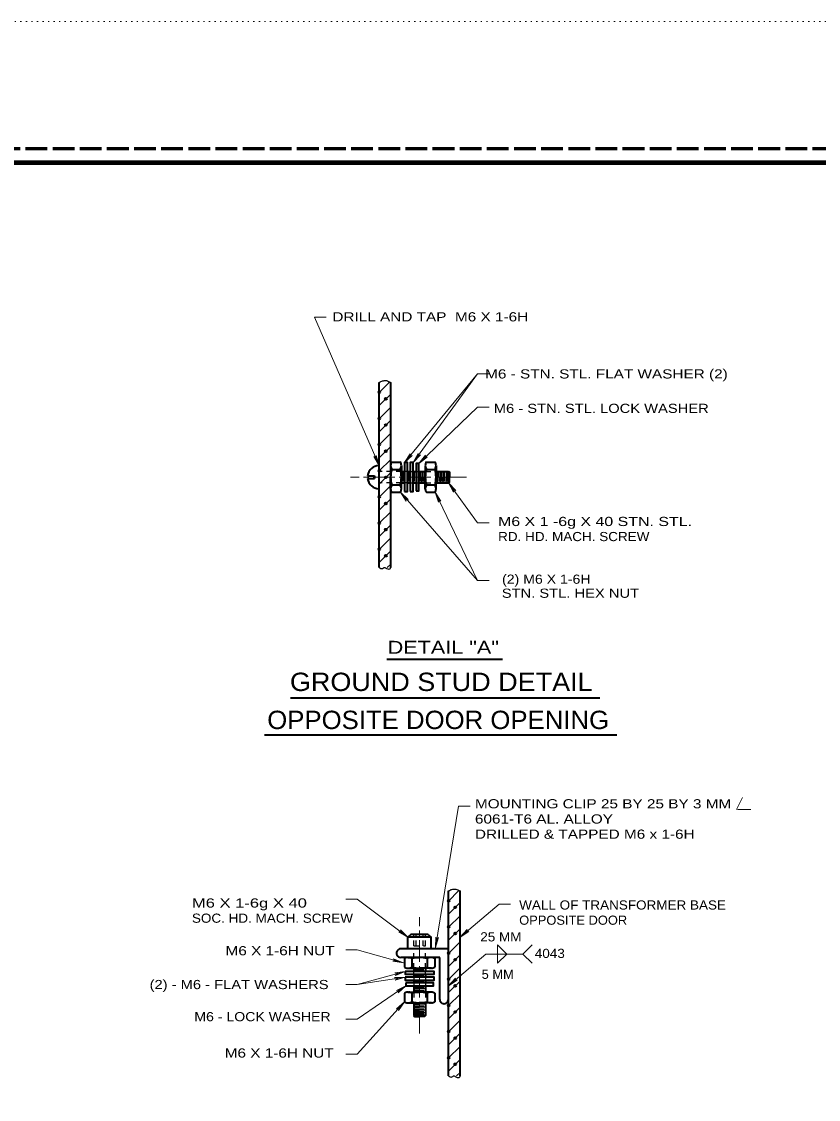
# Model space of a CAD drawing. Extents: x 312583 to 312854, y 144419 to 144597.
# Drawn here: x 312721.4 to 312787.4, y 144507.4 to 144596.8 of the extents above; entities that cross this region are included whole.
import ezdxf
from ezdxf.enums import TextEntityAlignment as Align

# ---------------------------------------------------------------- set-up
doc = ezdxf.new("R2010")
doc.units = 0
doc.header["$LTSCALE"] = 0.3
doc.header["$PDMODE"] = 32
doc.header["$PDSIZE"] = 0.15
for name, pattern in [('DOTTED', [1.5, 0.3, -1.2]), ('LONG_DASH_SHORT_DASH', [9.9, 6, -1.2, 1.5, -1.2]), ('LONG_DASHED', [7.5, 6, -1.5]), ('SHORT_DASHED', [2.7, 1.5, -1.2])]:
    doc.linetypes.add(name, pattern=pattern)
for name, color, linetype, lineweight in [('1', 7, 'Continuous', 40), ('2', 7, 'Continuous', 13), ('62', 7, 'DOTTED', 13), ('63', 7, 'LONG_DASHED', 60)]:
    doc.layers.add(name, color=color, linetype=linetype, lineweight=lineweight)

msp = doc.modelspace()

# ---------------------------------------------------------------- linework, layer by layer
at = {"layer": '1', "lineweight": 35}
for p, q in [((312751.013, 144551.5207), (312751.013, 144566.854)), ((312751.9713, 144551.5207), (312751.9713, 144566.854)), ((312751.9637, 144559.9847), (312751.9637, 144559.0033)), ((312752.0557, 144560.2607), (312752.7763, 144560.2607)), ((312752.8607, 144559.9847), (312752.8607, 144559.0033)), ((312754.8387, 144559.9847), (312754.8387, 144559.0033)), ((312754.9307, 144560.2607), (312755.6513, 144560.2607)), ((312755.7357, 144559.9847), (312755.7357, 144559.0033)), ((312750.0547, 144559.126), (312750.6143, 144559.126)), ((312750.0547, 144558.8883), (312750.6143, 144558.8883)), ((312750.6143, 144559.126), (312750.6143, 144558.8883)), ((312751.9637, 144558.022), (312751.9637, 144559.0033)), ((312752.0557, 144559.632), (312752.7763, 144559.632)), ((312752.8607, 144558.022), (312752.8607, 144559.0033)), ((312752.876, 144559.4863), (312753.1213, 144559.4863)), ((312753.359, 144559.4863), (312753.5967, 144559.4863)), ((312753.8343, 144559.4863), (312754.072, 144559.4863)), ((312754.3097, 144559.4863), (312754.8387, 144559.4863)), ((312754.8387, 144558.022), (312754.8387, 144559.0033)), ((312754.9307, 144559.632), (312755.6513, 144559.632)), ((312755.7357, 144559.4863), (312756.763, 144559.4863)), ((312755.7357, 144558.022), (312755.7357, 144559.0033)), ((312756.763, 144559.4863), (312756.763, 144559.0033)), ((312756.763, 144558.528), (312756.763, 144559.0033)), ((312752.0557, 144558.3747), (312752.7763, 144558.3747)), ((312752.876, 144558.528), (312753.1213, 144558.528)), ((312753.359, 144558.528), (312753.5967, 144558.528)), ((312753.8343, 144558.528), (312754.072, 144558.528)), ((312754.3097, 144558.528), (312754.8387, 144558.528)), ((312754.9307, 144558.3747), (312755.6513, 144558.3747)), ((312755.7357, 144558.528), (312756.763, 144558.528)), ((312752.0557, 144557.746), (312752.7763, 144557.746)), ((312754.9307, 144557.746), (312755.6513, 144557.746)), ((312756.763, 144509.354), (312756.763, 144524.6873)), ((312757.7213, 144509.354), (312757.7213, 144524.6873)), ((312753.405, 144519.8957), (312753.405, 144520.854)), ((312755.084, 144521.0917), (312755.3217, 144520.854)), ((312756.763, 144519.8957), (312752.807, 144519.8957)), ((312756.0423, 144519.175), (312752.807, 144519.175)), ((312753.106, 144519.0907), (312753.106, 144518.37)), ((312753.382, 144519.175), (312754.3633, 144519.175)), ((312753.7347, 144519.0907), (312753.7347, 144518.37)), ((312755.3447, 144519.175), (312754.3633, 144519.175)), ((312754.992, 144519.0907), (312754.992, 144518.37)), ((312755.6207, 144519.0907), (312755.6207, 144518.37)), ((312756.0423, 144515.702), (312756.0423, 144519.175)), ((312753.382, 144518.278), (312754.3633, 144518.278)), ((312753.888, 144518.2627), (312753.888, 144518.025)), ((312753.888, 144517.7797), (312753.888, 144517.5497)), ((312755.3447, 144518.278), (312754.3633, 144518.278)), ((312754.8463, 144518.2627), (312754.8463, 144518.025)), ((312754.8463, 144517.7797), (312754.8463, 144517.5497)), ((312753.888, 144517.312), (312753.888, 144517.0667)), ((312753.888, 144516.829), (312753.888, 144516.3)), ((312754.8463, 144517.312), (312754.8463, 144517.0667)), ((312754.8463, 144516.829), (312754.8463, 144516.3)), ((312753.106, 144516.2157), (312753.106, 144515.495)), ((312753.382, 144516.3), (312754.3633, 144516.3)), ((312753.7347, 144516.2157), (312753.7347, 144515.495)), ((312755.3447, 144516.3), (312754.3633, 144516.3)), ((312754.992, 144516.2157), (312754.992, 144515.495)), ((312755.6207, 144516.2157), (312755.6207, 144515.495)), ((312753.382, 144515.403), (312754.3633, 144515.403)), ((312753.888, 144515.403), (312753.888, 144514.3757)), ((312755.3447, 144515.403), (312754.3633, 144515.403)), ((312754.8463, 144515.403), (312754.8463, 144514.3757)), ((312753.888, 144514.3757), (312754.3633, 144514.3757)), ((312754.8463, 144514.3757), (312754.3633, 144514.3757))]:
    msp.add_line(p, q, dxfattribs=at)
at = {"layer": '1', "lineweight": 13}
for p, q in [((312751.013, 144566.0183), (312751.8487, 144566.854)), ((312751.013, 144564.9373), (312751.9713, 144565.8957)), ((312751.013, 144563.8487), (312751.9713, 144564.807)), ((312751.013, 144562.7677), (312751.9713, 144563.726)), ((312751.0053, 144561.679), (312751.9713, 144562.645)), ((312751.013, 144560.598), (312751.9713, 144561.5563)), ((312751.013, 144559.517), (312751.9713, 144560.4753)), ((312751.013, 144558.4283), (312751.9713, 144559.3867)), ((312751.013, 144557.3473), (312751.9713, 144558.3057)), ((312751.013, 144556.2663), (312751.9713, 144557.217)), ((312751.013, 144555.1777), (312751.9713, 144556.136)), ((312751.013, 144554.089), (312751.9713, 144555.055)), ((312751.013, 144553.008), (312751.9713, 144553.9663)), ((312751.013, 144551.927), (312751.9713, 144552.8853)), ((312751.6877, 144551.5207), (312751.9713, 144551.7967)), ((312756.763, 144523.8517), (312757.5987, 144524.6873)), ((312756.763, 144522.7707), (312757.7213, 144523.729)), ((312756.763, 144521.682), (312757.7213, 144522.6403)), ((312756.763, 144520.601), (312757.7213, 144521.5593)), ((312756.7553, 144519.5123), (312757.7213, 144520.4783)), ((312756.763, 144518.4313), (312757.7213, 144519.3897)), ((312756.763, 144517.3503), (312757.7213, 144518.3087)), ((312756.763, 144516.2617), (312757.7213, 144517.22)), ((312756.763, 144515.1807), (312757.7213, 144516.139)), ((312756.763, 144514.0997), (312757.7213, 144515.0503)), ((312756.763, 144513.011), (312757.7213, 144513.9693)), ((312756.763, 144511.9223), (312757.7213, 144512.8883)), ((312756.763, 144510.8413), (312757.7213, 144511.7997)), ((312756.763, 144509.7603), (312757.7213, 144510.7187)), ((312757.4377, 144509.354), (312757.7213, 144509.63))]:
    msp.add_line(p, q, dxfattribs=at)
at = {"layer": '1', "linetype": 'LONG_DASH_SHORT_DASH', "lineweight": 13}
for p, q in [((312758.2657, 144559.0033), (312748.6363, 144559.0033)), ((312754.3633, 144512.873), (312754.3633, 144522.51))]:
    msp.add_line(p, q, dxfattribs=at)
at = {"layer": '1', "linetype": 'SHORT_DASHED', "lineweight": 25}
for p, q in [((312752.876, 144559.4863), (312751.013, 144559.4863)), ((312753.359, 144559.4863), (312753.1213, 144559.4863)), ((312753.5967, 144559.4863), (312753.8343, 144559.4863)), ((312754.072, 144559.4863), (312754.3097, 144559.4863)), ((312754.8387, 144559.4863), (312755.7357, 144559.4863)), ((312752.876, 144558.528), (312751.013, 144558.528)), ((312753.359, 144558.528), (312753.1213, 144558.528)), ((312753.5967, 144558.528), (312753.8343, 144558.528)), ((312754.072, 144558.528), (312754.3097, 144558.528)), ((312754.8387, 144558.528), (312755.7357, 144558.528)), ((312753.888, 144520.1333), (312753.888, 144521.0917)), ((312754.0873, 144520.1333), (312754.0873, 144521.0917)), ((312754.6623, 144520.1333), (312754.6623, 144521.0917)), ((312754.8463, 144520.1333), (312754.8463, 144521.0917)), ((312753.888, 144520.1333), (312754.8463, 144520.1333)), ((312753.888, 144518.2627), (312753.888, 144519.8957)), ((312754.8463, 144518.2627), (312754.8463, 144519.8957)), ((312753.888, 144517.7797), (312753.888, 144518.025)), ((312754.8463, 144517.7797), (312754.8463, 144518.025)), ((312753.888, 144517.5497), (312753.888, 144517.312)), ((312753.888, 144517.0667), (312753.888, 144516.829)), ((312754.8463, 144517.5497), (312754.8463, 144517.312)), ((312754.8463, 144517.0667), (312754.8463, 144516.829)), ((312753.888, 144516.3), (312753.888, 144515.403)), ((312754.8463, 144516.3), (312754.8463, 144515.403))]:
    msp.add_line(p, q, dxfattribs=at)
at = {"layer": '1', "lineweight": 25}
for p, q in [((312752.9987, 144559.3637), (312752.9987, 144559.0033)), ((312752.9987, 144558.643), (312752.9987, 144559.0033)), ((312753.474, 144559.3637), (312753.474, 144559.0033)), ((312753.474, 144558.643), (312753.474, 144559.3637)), ((312753.474, 144558.643), (312753.474, 144559.0033)), ((312753.957, 144558.643), (312753.957, 144559.3637)), ((312754.4323, 144558.643), (312754.4323, 144559.3637)), ((312754.5473, 144559.4863), (312754.5473, 144559.0033)), ((312754.5473, 144558.5203), (312754.5473, 144559.0033)), ((312754.67, 144558.643), (312754.67, 144559.3637)), ((312754.785, 144559.4863), (312754.785, 144559.0033)), ((312754.785, 144558.5203), (312754.785, 144559.0033)), ((312755.8507, 144559.4863), (312755.8507, 144559.0033)), ((312755.8507, 144558.5203), (312755.8507, 144559.0033)), ((312755.981, 144558.643), (312755.981, 144559.3637)), ((312756.0883, 144559.4863), (312756.0883, 144559.0033)), ((312756.0883, 144558.5203), (312756.0883, 144559.0033)), ((312756.2187, 144558.643), (312756.2187, 144559.3637)), ((312756.326, 144559.4863), (312756.326, 144559.0033)), ((312756.326, 144558.5203), (312756.326, 144559.0033)), ((312756.441, 144558.643), (312756.441, 144559.3637)), ((312756.5637, 144559.4863), (312756.5637, 144559.0033)), ((312756.5637, 144558.5203), (312756.5637, 144559.0033)), ((312756.6557, 144558.643), (312756.6557, 144559.3637)), ((312754.003, 144518.14), (312754.3633, 144518.14)), ((312754.7237, 144518.14), (312754.3633, 144518.14)), ((312754.003, 144517.6647), (312754.3633, 144517.6647)), ((312754.003, 144517.6647), (312754.7237, 144517.6647)), ((312754.003, 144517.1893), (312754.7237, 144517.1893)), ((312754.7237, 144517.6647), (312754.3633, 144517.6647)), ((312753.8803, 144516.599), (312754.3633, 144516.599)), ((312753.8803, 144516.3613), (312754.3633, 144516.3613)), ((312754.003, 144516.7063), (312754.7237, 144516.7063)), ((312754.003, 144516.4687), (312754.7237, 144516.4687)), ((312754.8463, 144516.599), (312754.3633, 144516.599)), ((312754.8463, 144516.3613), (312754.3633, 144516.3613)), ((312753.8803, 144515.2957), (312754.3633, 144515.2957)), ((312753.8803, 144515.0503), (312754.3633, 144515.0503)), ((312754.003, 144515.1653), (312754.7237, 144515.1653)), ((312754.8463, 144515.2957), (312754.3633, 144515.2957)), ((312754.8463, 144515.0503), (312754.3633, 144515.0503)), ((312753.8803, 144514.8127), (312754.3633, 144514.8127)), ((312753.8803, 144514.575), (312754.3633, 144514.575)), ((312754.003, 144514.9277), (312754.7237, 144514.9277)), ((312754.003, 144514.7053), (312754.7237, 144514.7053)), ((312754.003, 144514.4907), (312754.7237, 144514.4907)), ((312754.8463, 144514.8127), (312754.3633, 144514.8127)), ((312754.8463, 144514.575), (312754.3633, 144514.575))]:
    msp.add_line(p, q, dxfattribs=at)
at = {"layer": '1', "lineweight": 158}
msp.add_lwpolyline([(312616.5, 144423.1446), (312616.5, 144585.0846), (312849, 144585.0846)], dxfattribs=at)
at = {"layer": '1', "lineweight": 35}
for points in [[(312753.1213, 144557.8073), (312753.359, 144557.8073), (312753.359, 144560.207), (312753.1213, 144560.207)], [(312753.5967, 144557.8073), (312753.8343, 144557.8073), (312753.8343, 144560.207), (312753.5967, 144560.207)], [(312754.072, 144557.8687), (312754.3097, 144557.8687), (312754.3097, 144560.1457), (312754.072, 144560.1457)], [(312753.1673, 144518.0173), (312753.1673, 144517.7797), (312755.567, 144517.7797), (312755.567, 144518.0173)], [(312753.1673, 144517.542), (312753.1673, 144517.3043), (312755.567, 144517.3043), (312755.567, 144517.542)], [(312753.2287, 144517.0667), (312753.2287, 144516.829), (312755.5057, 144516.829), (312755.5057, 144517.0667)]]:
    msp.add_lwpolyline(points, close=True, dxfattribs=at)
for points in [[(312756.763, 144559.4863), (312756.8473, 144559.425), (312756.8473, 144559.0033)], [(312756.763, 144558.528), (312756.8473, 144558.5893), (312756.8473, 144559.0033)], [(312755.084, 144521.0917), (312753.6503, 144521.0917), (312753.405, 144520.854)], [(312755.3217, 144519.8957), (312755.3217, 144520.854), (312753.405, 144520.854)], [(312753.888, 144514.3757), (312753.9493, 144514.2913), (312754.3633, 144514.2913)], [(312754.8463, 144514.3757), (312754.785, 144514.2913), (312754.3633, 144514.2913)]]:
    msp.add_lwpolyline(points, dxfattribs=at)
for centre, radius, start, end in [((312751.0067, 144559.0033), 0.9583, 89.85149, 172.64599), ((312753.4169, 144560.2211), 1.4854, 191.77014, 203.36365), ((312752.4827, 144559.9706), 0.5187, 145.8703, 178.33743), ((312752.3397, 144559.9706), 0.5187, 1.66257, 34.1297), ((312751.4055, 144560.2211), 1.4854, 336.63635, 348.22986), ((312756.2919, 144560.2211), 1.4854, 191.77014, 203.36365), ((312755.3577, 144559.9706), 0.5187, 145.8703, 178.33743), ((312755.2147, 144559.9706), 0.5187, 1.66257, 34.1297), ((312754.2805, 144560.2211), 1.4854, 336.63635, 348.22986), ((312751.0067, 144559.0033), 0.9583, 187.12299, 270.14851), ((312754.6426, 144558.9381), 2.6807, 164.99798, 178.595), ((312754.6426, 144559.0695), 2.6807, 181.405, 195.00202), ((312750.1798, 144558.9381), 2.6807, 1.405, 15.00202), ((312750.1798, 144559.0695), 2.6807, 344.99798, 358.595), ((312757.5176, 144558.9381), 2.6807, 164.99798, 178.595), ((312757.5176, 144559.0695), 2.6807, 181.405, 195.00202), ((312753.0548, 144558.9381), 2.6807, 1.405, 15.00202), ((312753.0548, 144559.0695), 2.6807, 344.99798, 358.595), ((312753.4169, 144557.7866), 1.4854, 156.63635, 168.22986), ((312752.4827, 144558.0371), 0.5187, 181.66257, 214.1297), ((312751.4055, 144557.7866), 1.4854, 11.77014, 23.36365), ((312752.3397, 144558.0371), 0.5187, 325.8703, 358.33743), ((312756.2919, 144557.7866), 1.4854, 156.63635, 168.22986), ((312755.3577, 144558.0371), 0.5187, 181.66257, 214.1297), ((312754.2805, 144557.7866), 1.4854, 11.77014, 23.36365), ((312755.2147, 144558.0371), 0.5187, 325.8703, 358.33743), ((312752.8051, 144519.5334), 0.3584, 89.69361, 270.30639), ((312753.3971, 144518.656), 0.5187, 91.66257, 124.1297), ((312753.1466, 144517.7218), 1.4854, 66.63635, 78.22986), ((312754.4295, 144516.496), 2.6807, 91.405, 105.00202), ((312754.2981, 144516.496), 2.6807, 74.99798, 88.595), ((312755.5811, 144517.7218), 1.4854, 101.77014, 113.36365), ((312755.3306, 144518.656), 0.5187, 55.8703, 88.33743), ((312753.3971, 144518.7989), 0.5187, 235.8703, 268.33743), ((312753.1466, 144519.7331), 1.4854, 281.77014, 293.36365), ((312754.4295, 144520.9589), 2.6807, 254.99798, 268.595), ((312754.2981, 144520.9589), 2.6807, 271.405, 285.00202), ((312755.5811, 144519.7331), 1.4854, 246.63635, 258.22986), ((312755.3306, 144518.7989), 0.5187, 271.66257, 304.1297), ((312753.3971, 144515.781), 0.5187, 91.66257, 124.1297), ((312753.1466, 144514.8468), 1.4854, 66.63635, 78.22986), ((312754.4295, 144513.621), 2.6807, 91.405, 105.00202), ((312754.2981, 144513.621), 2.6807, 74.99798, 88.595), ((312755.5811, 144514.8468), 1.4854, 101.77014, 113.36365), ((312755.3306, 144515.781), 0.5187, 55.8703, 88.33743), ((312753.3971, 144515.9239), 0.5187, 235.8703, 268.33743), ((312753.1466, 144516.8581), 1.4854, 281.77014, 293.36365), ((312754.4295, 144518.0839), 2.6807, 254.99798, 268.595), ((312754.2981, 144518.0839), 2.6807, 271.405, 285.00202), ((312755.5811, 144516.8581), 1.4854, 246.63635, 258.22986), ((312755.3306, 144515.9239), 0.5187, 271.66257, 304.1297), ((312756.4008, 144515.7001), 0.3584, 179.69361, 0.30639)]:
    msp.add_arc(centre, radius, start, end, dxfattribs=at)
at = {"layer": '1', "lineweight": 25}
for points in [[(312751.013, 144566.854), (312751.1663, 144566.946), (312751.4347, 144567.0073), (312751.611, 144567.0073), (312751.9713, 144566.854)], [(312751.013, 144551.5207), (312751.289, 144551.4363), (312751.4347, 144551.5207), (312751.634, 144551.4363), (312751.956, 144551.4363), (312751.9713, 144551.5207)], [(312756.763, 144524.6873), (312756.9163, 144524.7793), (312757.1847, 144524.8407), (312757.361, 144524.8407), (312757.7213, 144524.6873)], [(312756.763, 144509.354), (312757.039, 144509.2697), (312757.1847, 144509.354), (312757.384, 144509.2697), (312757.706, 144509.2697), (312757.7213, 144509.354)]]:
    msp.add_spline(points, degree=3, dxfattribs=at)
at = {"layer": '1'}
for p in [(312751.0283, 144566.0413), (312751.5727, 144565.497), (312751.0283, 144563.8717), (312751.5727, 144563.3273), (312751.0283, 144561.702), (312751.5727, 144561.1577), (312751.0283, 144559.5323), (312751.5727, 144558.988), (312751.0283, 144557.3627), (312751.5727, 144556.8183), (312751.0283, 144555.193), (312751.5727, 144554.6563), (312751.0283, 144553.0233), (312751.5727, 144552.4867), (312756.7783, 144523.8747), (312757.3227, 144523.3303), (312756.7783, 144521.705), (312757.3227, 144521.1607), (312756.7783, 144519.5353), (312757.3227, 144518.991), (312756.7783, 144517.3657), (312757.3227, 144516.8213), (312756.7783, 144515.196), (312757.3227, 144514.6517), (312756.7783, 144513.0263), (312757.3227, 144512.4897), (312756.7783, 144510.8567), (312757.3227, 144510.32)]:
    msp.add_point(p, dxfattribs=at)
at = {"layer": '2'}
for p, q in [((312745.6617, 144572.2667), (312751.013, 144559.9617)), ((312745.6617, 144572.2667), (312746.62, 144572.2667)), ((312759.1703, 144567.5823), (312753.1213, 144560.207)), ((312759.1703, 144567.5823), (312753.8343, 144560.207)), ((312759.1703, 144567.5823), (312760.1287, 144567.5823)), ((312759.1703, 144564.8147), (312754.3097, 144560.1457)), ((312759.1703, 144564.8147), (312760.1287, 144564.8147)), ((312750.5683, 144560.713), (312750.7753, 144560.506)), ((312751.013, 144559.9617), (312750.5683, 144560.713)), ((312750.7677, 144560.7973), (312750.7753, 144560.506)), ((312751.013, 144559.9617), (312750.7677, 144560.7973)), ((312753.1213, 144560.207), (312753.589, 144560.943)), ((312753.1213, 144560.207), (312753.7577, 144560.805)), ((312753.589, 144560.943), (312753.497, 144560.6593)), ((312753.7577, 144560.805), (312753.497, 144560.6593)), ((312753.8343, 144560.207), (312754.256, 144560.9737)), ((312753.8343, 144560.207), (312754.4323, 144560.8433)), ((312754.256, 144560.9737), (312754.1793, 144560.6823)), ((312754.4323, 144560.8433), (312754.1793, 144560.6823)), ((312754.3097, 144560.1457), (312754.8617, 144560.8203)), ((312754.3097, 144560.1457), (312755.0073, 144560.667)), ((312754.8617, 144560.8203), (312754.739, 144560.552)), ((312755.0073, 144560.667), (312754.739, 144560.552)), ((312759.1703, 144555.216), (312756.763, 144558.528)), ((312756.763, 144558.528), (312757.1847, 144557.7613)), ((312756.763, 144558.528), (312757.361, 144557.8917)), ((312757.1847, 144557.7613), (312757.1157, 144558.045)), ((312757.361, 144557.8917), (312757.1157, 144558.045)), ((312759.1703, 144550.4473), (312752.7763, 144557.746)), ((312752.7763, 144557.746), (312753.267, 144557.0253)), ((312752.7763, 144557.746), (312753.428, 144557.1633)), ((312753.267, 144557.0253), (312753.1673, 144557.3013)), ((312753.428, 144557.1633), (312753.1673, 144557.3013)), ((312759.1703, 144550.4473), (312755.6513, 144557.746)), ((312755.6513, 144557.746), (312755.9273, 144556.918)), ((312755.6513, 144557.746), (312756.119, 144557.0177)), ((312755.9273, 144556.918), (312755.9043, 144557.217)), ((312756.119, 144557.0177), (312755.9043, 144557.217)), ((312759.1703, 144555.216), (312760.1287, 144555.216)), ((312759.1703, 144550.4473), (312760.1287, 144550.4473)), ((312780.6442, 144531.4581), (312781.1502, 144532.4394)), ((312755.6897, 144519.9877), (312757.591, 144531.7253)), ((312757.591, 144531.7253), (312758.5493, 144531.7253)), ((312780.7132, 144531.4581), (312781.8402, 144531.4581)), ((312749.196, 144524.0203), (312748.2377, 144524.0203)), ((312749.196, 144524.0203), (312753.405, 144520.854)), ((312752.6537, 144521.291), (312752.9373, 144521.2067)), ((312753.405, 144520.854), (312752.6537, 144521.291)), ((312752.7763, 144521.4597), (312752.9373, 144521.2067)), ((312753.405, 144520.854), (312752.7763, 144521.4597)), ((312757.7213, 144520.854), (312758.3117, 144521.498)), ((312757.7213, 144520.854), (312758.4497, 144521.3293)), ((312758.3117, 144521.498), (312758.1737, 144521.2373)), ((312758.4497, 144521.3293), (312758.1737, 144521.2373)), ((312755.6897, 144519.9877), (312755.7203, 144520.8617)), ((312755.6897, 144519.9877), (312755.935, 144520.8233)), ((312755.7203, 144520.8617), (312755.7893, 144520.5703)), ((312755.935, 144520.8233), (312755.7893, 144520.5703)), ((312749.196, 144519.8037), (312748.2377, 144519.8037)), ((312749.196, 144519.8037), (312753.0217, 144518.7303)), ((312763.7013, 144520.2253), (312762.9347, 144519.4587)), ((312752.1553, 144518.8607), (312752.4543, 144518.8913)), ((312753.0217, 144518.7303), (312752.1553, 144518.8607)), ((312752.2167, 144519.0677), (312752.4543, 144518.8913)), ((312753.0217, 144518.7303), (312752.2167, 144519.0677)), ((312763.7013, 144518.692), (312762.9347, 144519.4587)), ((312749.196, 144516.9363), (312753.1673, 144518.0173)), ((312753.1673, 144518.0173), (312752.3087, 144517.8947)), ((312752.3087, 144517.8947), (312752.6, 144517.864)), ((312753.1673, 144518.0173), (312752.3623, 144517.6877)), ((312752.3623, 144517.6877), (312752.6, 144517.864)), ((312749.196, 144516.9363), (312748.2377, 144516.9363)), ((312749.196, 144516.9363), (312753.1673, 144517.542)), ((312749.196, 144514.046), (312753.2287, 144516.829)), ((312753.1673, 144517.542), (312752.2933, 144517.519)), ((312753.1673, 144517.542), (312752.2933, 144517.519)), ((312752.2933, 144517.519), (312752.5847, 144517.4577)), ((312752.2933, 144517.519), (312752.5847, 144517.4577)), ((312753.1673, 144517.542), (312752.3317, 144517.3043)), ((312753.1673, 144517.542), (312752.3317, 144517.3043)), ((312752.3317, 144517.3043), (312752.5847, 144517.4577)), ((312752.3317, 144517.3043), (312752.5847, 144517.4577)), ((312753.2287, 144516.829), (312752.4543, 144516.4303)), ((312753.2287, 144516.829), (312752.577, 144516.254)), ((312756.763, 144516.8213), (312757.3533, 144517.4653)), ((312756.763, 144516.8213), (312757.4913, 144517.3043)), ((312757.3533, 144517.4653), (312757.2077, 144517.2047)), ((312757.4913, 144517.3043), (312757.2077, 144517.2047)), ((312752.4543, 144516.4303), (312752.7457, 144516.4993)), ((312752.577, 144516.254), (312752.7457, 144516.4993)), ((312749.196, 144511.1557), (312753.106, 144515.495)), ((312753.106, 144515.495), (312752.4467, 144514.92)), ((312752.4467, 144514.92), (312752.715, 144515.058)), ((312753.106, 144515.495), (312752.6077, 144514.7743)), ((312752.6077, 144514.7743), (312752.715, 144515.058)), ((312749.196, 144514.046), (312748.2377, 144514.046)), ((312749.196, 144511.1557), (312748.2377, 144511.1557))]:
    msp.add_line(p, q, dxfattribs=at)
at = {"layer": '2', "lineweight": 35}
msp.add_line((312751.653, 144543.9), (312761.2516, 144543.9), dxfattribs=at)
at = {"layer": '2', "lineweight": 40}
for p, q in [((312743.6732, 144540.7112), (312769.3161, 144540.7112)), ((312741.5012, 144537.6257), (312770.7174, 144537.6257))]:
    msp.add_line(p, q, dxfattribs=at)
at = {"layer": '2'}
for points in [[(312757.7213, 144520.854), (312760.9567, 144523.5987), (312761.915, 144523.5987)], [(312760.8263, 144519.4587), (312760.8263, 144520.2253), (312761.593, 144519.4587)], [(312756.763, 144516.8213), (312759.868, 144519.4587), (312760.8263, 144519.4587), (312762.9347, 144519.4587)], [(312760.8263, 144519.4587), (312760.8263, 144518.692), (312761.593, 144519.4587)]]:
    msp.add_lwpolyline(points, dxfattribs=at)
at = {"layer": '62'}
msp.add_line((312601.2, 144596.7846), (312853.5, 144596.7846), dxfattribs=at)
at = {"layer": '63'}
msp.add_line((312851.75, 144586.2246), (312583.526, 144586.2246), dxfattribs=at)

# ---------------------------------------------------------------- texts
at = {"layer": '2'}
for s, width, p in [('DRILL AND TAP  M6 X 1-6H', 1.25, (312747.1337, 144571.9199)), ('M6 - STN. STL. FLAT WASHER (2)', 1.25, (312759.799, 144567.1873)), ('M6 - STN. STL. LOCK WASHER', 1.2, (312760.5165, 144564.3288)), ('M6 X 1 -6g X 40 STN. STL.', 1.3, (312760.8711, 144554.9501)), ('RD. HD. MACH. SCREW', 1.1, (312760.8758, 144553.6997)), ('(2) M6 X 1-6H', 1.15, (312761.2029, 144550.1643)), ('STN. STL. HEX NUT', 1.2, (312761.1789, 144549.0013)), ('MOUNTING CLIP 25 BY 25 BY 3 MM', 1.25, (312758.9557, 144531.5403)), ('6061-T6 AL. ALLOY', 1.25, (312758.9557, 144530.2803)), ('DRILLED & TAPPED M6 x 1-6H', 1.25, (312758.9557, 144529.0203)), ('M6 X 1-6g X 40', 1.35, (312735.4903, 144523.3127)), ('WALL OF TRANSFORMER BASE', 1.1, (312762.6238, 144523.1475)), ('SOC. HD. MACH. SCREW', 1.1, (312735.4903, 144522.0527)), ('OPPOSITE DOOR', 1.05, (312762.6238, 144521.8875)), ('25 MM', 1.1, (312759.3966, 144520.5073)), ('M6 X 1-6H NUT', 1.25, (312738.2796, 144519.355)), ('4043', 1.1, (312763.919, 144519.1326)), ('5 MM', 1.05, (312759.5112, 144517.4011)), ('(2) - M6 - FLAT WASHERS', 1.2, (312731.9815, 144516.5513)), ('M6 - LOCK WASHER', 1.15, (312735.6896, 144513.8868)), ('M6 X 1-6H NUT', 1.25, (312738.2096, 144510.8714))]:
    msp.add_text(s, height=0.76, dxfattribs=dict(at, width=width)).set_placement(p)
for s, height, width, p in [('DETAIL "A"', 1.07, 1.25, (312756.3335, 144544.3621)), ('GROUND STUD DETAIL', 1.52, 1.1, (312756.1634, 144541.2716)), ('OPPOSITE DOOR OPENING', 1.52, 1.05, (312755.9063, 144538.1159))]:
    msp.add_text(s, height=height, dxfattribs=dict(at, width=width)).set_placement(p, align=Align.CENTER)

doc.saveas('drawing.dxf')
